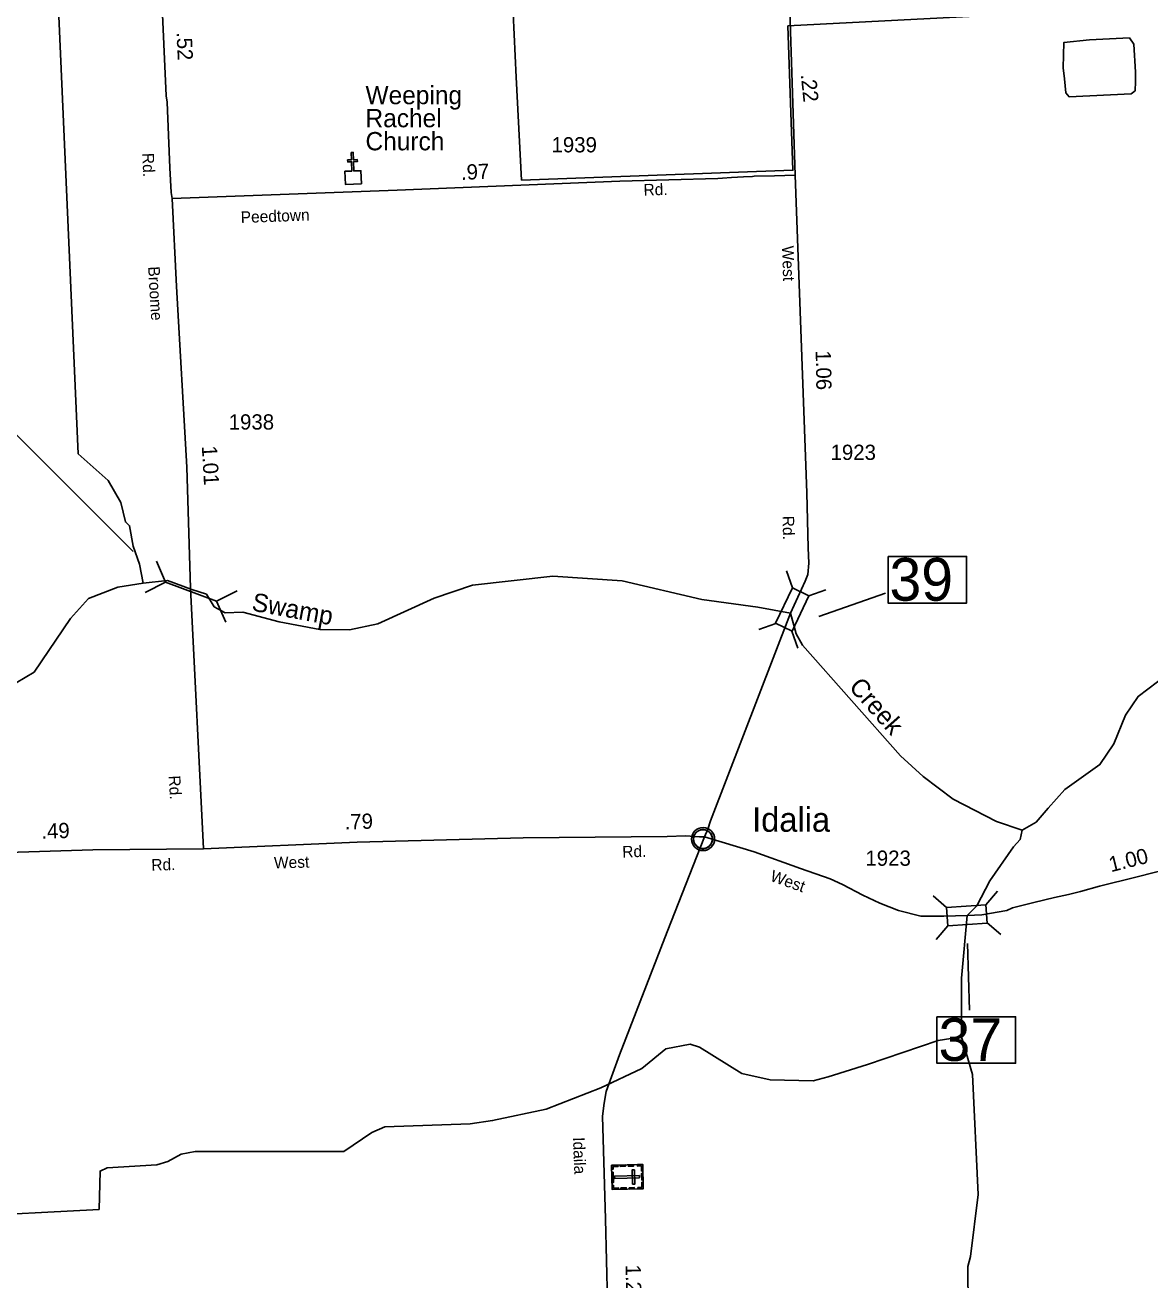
# Model space of a CAD drawing. Extents: x 2532689 to 2764727, y 536648 to 732970.
# Drawn here: x 2653505 to 2662724, y 560516 to 570801 of the extents above; entities that cross this region are included whole.
import ezdxf

# ---------------------------------------------------------------- set-up
doc = ezdxf.new("R2010")
doc.units = 0
for name, color, linetype in [('Exist Boundary Political City Limit New', 7, 'Continuous'), ('Exist Civil Demographics Community CELL', 7, 'Continuous'), ('Exist Civil Demographics Community Label', 7, 'Continuous'), ('Exist Cultural Cemetery CELL', 7, 'Continuous'), ('Exist Cultural Church CELL', 7, 'Continuous'), ('Exist Cultural Church Label', 7, 'Continuous'), ('Exist Hydrographic Creek Single Shore', 7, 'Continuous'), ('Exist Hydrographic Creek Single Shore Label', 7, 'Continuous'), ('Exist Hydrographic Pond Under 1500 Sq Ft', 7, 'Continuous'), ('Exist Road Secondary Mileage Hundredths English Label', 7, 'Continuous'), ('Exist Road Secondary Structure Pipe CELL', 7, 'Continuous'), ('Exist Road Secondary Structure Pipe Number Label', 7, 'Continuous'), ('Exist Road Secondary Structure Standard Bridge CELL', 7, 'Continuous'), ('Exist Road Secondary Structure Standard Bridge Number Label', 7, 'Continuous'), ('Exist Road Secondary Type 20 Attributed', 7, 'Continuous'), ('Exist Road Secondary Type 51 Attributed', 7, 'Continuous'), ('Exist Road Secondary Type 51 Label', 7, 'Continuous'), ('Exist Road Secondary Type 51 Number Label', 7, 'Continuous'), ('Map Preparation Boundary City Limit Buffer Line', 7, 'Continuous')]:
    doc.layers.add(name, color=color, linetype=linetype)

msp = doc.modelspace()

# ---------------------------------------------------------------- linework, layer by layer
at = {"layer": 'Exist Boundary Political City Limit New'}
for points in [[(2659756, 570796), (2659798, 569611), (2657575, 569531), (2657530, 570375), (2657498, 571076)], [(2663735, 571000), (2659756, 570796)]]:
    msp.add_lwpolyline(points, dxfattribs=at)
at = {"layer": 'Exist Civil Demographics Community CELL'}
msp.add_lwpolyline([(2658984, 564141), (2658985, 564147), (2658987, 564154), (2658990, 564161), (2658993, 564167), (2658996, 564172), (2659000, 564177), (2659004, 564182), (2659008, 564186), (2659014, 564191), (2659019, 564195), (2659024, 564198), (2659029, 564200), (2659035, 564202), (2659040, 564204), (2659044, 564205), (2659049, 564206), (2659053, 564207), (2659060, 564207), (2659064, 564207), (2659070, 564207), (2659075, 564206), (2659080, 564205), (2659085, 564203), (2659090, 564202), (2659097, 564199), (2659103, 564195), (2659108, 564192), (2659113, 564188), (2659116, 564184), (2659120, 564180), (2659124, 564175), (2659127, 564171), (2659131, 564166), (2659133, 564161), (2659135, 564156), (2659137, 564151), (2659138, 564146), (2659139, 564140), (2659140, 564135), (2659140, 564129), (2659140, 564123), (2659139, 564118), (2659138, 564112), (2659137, 564106), (2659135, 564100), (2659132, 564095), (2659129, 564089), (2659126, 564084), (2659122, 564079), (2659118, 564074), (2659113, 564069), (2659108, 564065), (2659103, 564062), (2659099, 564059), (2659092, 564056), (2659085, 564053), (2659079, 564052), (2659072, 564051), (2659068, 564050), (2659063, 564050), (2659058, 564050), (2659053, 564050), (2659048, 564051), (2659042, 564052), (2659037, 564054), (2659032, 564056), (2659027, 564058), (2659023, 564060), (2659017, 564064), (2659011, 564068), (2659006, 564073), (2659002, 564078), (2658999, 564081), (2658996, 564086), (2658991, 564093), (2658990, 564096), (2658988, 564100), (2658985, 564109), (2658984, 564116), (2658983, 564121), (2658983, 564127), (2658983, 564132), (2658983, 564138)], close=True, dxfattribs=at)
for centre, radius in [((2659062, 564129), 94.3), ((2659061, 564129), 76.7)]:
    msp.add_circle(centre, radius, dxfattribs=at)
at = {"layer": 'Exist Cultural Cemetery CELL'}
for points in [[(2658567, 561462), (2658572, 561263), (2658317, 561256), (2658312, 561455)], [(2658313, 561422), (2658325, 561423), (2658324, 561445), (2658365, 561446), (2658364, 561457), (2658312, 561455)], [(2658382, 561457), (2658426, 561458), (2658426, 561447), (2658383, 561446)], [(2658449, 561459), (2658493, 561460), (2658493, 561448), (2658450, 561447)], [(2658500, 561419), (2658481, 561419), (2658484, 561301), (2658503, 561301)], [(2658524, 561461), (2658524, 561449), (2658556, 561450), (2658557, 561409), (2658568, 561410), (2658567, 561462)], [(2658325, 561398), (2658327, 561313), (2658316, 561313), (2658314, 561398)], [(2658540, 561352), (2658540, 561371), (2658337, 561366), (2658338, 561347)], [(2658528, 561261), (2658528, 561273), (2658560, 561274), (2658559, 561314), (2658570, 561314), (2658572, 561263)], [(2658569, 561388), (2658570, 561336), (2658559, 561335), (2658557, 561387)], [(2658316, 561289), (2658328, 561290), (2658328, 561268), (2658369, 561269), (2658369, 561258), (2658317, 561256)], [(2658389, 561270), (2658432, 561271), (2658433, 561259), (2658389, 561258)], [(2658455, 561271), (2658498, 561272), (2658499, 561261), (2658455, 561260)]]:
    msp.add_lwpolyline(points, close=True, dxfattribs=at)
at = {"layer": 'Exist Cultural Church CELL'}
msp.add_lwpolyline([(2656127, 569603), (2656183, 569605), (2656181, 569681), (2656149, 569680), (2656148, 569696), (2656180, 569697), (2656178, 569757), (2656194, 569758), (2656196, 569698), (2656228, 569699), (2656229, 569683), (2656197, 569682), (2656199, 569606), (2656257, 569608), (2656261, 569501), (2656130, 569496)], close=True, dxfattribs=at)
at = {"layer": 'Exist Hydrographic Creek Single Shore'}
for points in [[(2654472, 566226), (2654443, 566383), (2654390, 566531), (2654361, 566698), (2654327, 566729), (2654290, 566889), (2654186, 567068), (2653940, 567288), (2653757, 571434), (2653723, 571837), (2653654, 572300), (2653667, 572458)], [(2661677, 564202), (2661467, 564273), (2661113, 564455), (2660867, 564642), (2660680, 564812), (2659876, 565719), (2659824, 565812), (2659779, 565981), (2659511, 566029), (2659051, 566093), (2658398, 566247), (2657830, 566283), (2657173, 566210), (2656858, 566103), (2656396, 565893), (2656165, 565845), (2655922, 565848), (2655587, 565910), (2655289, 565989), (2655144, 565983), (2655055, 566033), (2654991, 566136), (2654872, 566174), (2654672, 566249), (2654472, 566226)], [(2650468, 564078), (2650420, 565902), (2650469, 565920), (2651260, 565955), (2651562, 565885), (2651950, 565688), (2652300, 565652), (2653248, 565399), (2653431, 565409), (2653579, 565497), (2653878, 565936), (2654024, 566100), (2654264, 566195), (2654472, 566226)], [(2661677, 564202), (2661792, 564269), (2661890, 564382), (2662028, 564535), (2662315, 564740), (2662428, 564909), (2662523, 565146), (2662628, 565298), (2662866, 565478)], [(2661181, 562508), (2661179, 562990), (2661226, 563502), (2661307, 563583), (2661412, 563786), (2661605, 564065), (2661662, 564126), (2661677, 564202)], [(2652953, 561033), (2654111, 561093), (2654120, 561408), (2654178, 561434), (2654585, 561460), (2654676, 561487), (2654783, 561547), (2654900, 561568), (2656117, 561568), (2656347, 561725), (2656454, 561769), (2657154, 561794), (2657337, 561821), (2657776, 561914), (2658223, 562089), (2658561, 562248), (2658757, 562410), (2658957, 562448), (2659032, 562424), (2659379, 562208), (2659613, 562156), (2659963, 562147), (2660088, 562181), (2660411, 562280), (2660990, 562477), (2661181, 562508)], [(2661318, 561216), (2661271, 562199), (2661181, 562508)], [(2661344, 557744), (2661396, 557807), (2661487, 557947), (2661559, 558580), (2661555, 558773), (2661482, 559053), (2661456, 559088), (2661266, 559799), (2661237, 559956), (2661231, 560625), (2661254, 560708), (2661318, 561216)]]:
    msp.add_lwpolyline(points, dxfattribs=at)
at = {"layer": 'Exist Hydrographic Pond Under 1500 Sq Ft'}
for points in [[(2662606, 570415), (2662593, 570645), (2662556, 570696), (2662230, 570681), (2662019, 570659), (2662014, 570452), (2662024, 570360)], [(2662024, 570360), (2662036, 570246), (2662062, 570214), (2662571, 570238), (2662603, 570263), (2662605, 570339), (2662606, 570415)]]:
    msp.add_lwpolyline(points, dxfattribs=at)
at = {"layer": 'Exist Road Secondary Structure Pipe CELL'}
for p, q in [((2654582, 566407), (2654656, 566234)), ((2654488, 566151), (2654656, 566234)), ((2654656, 566234), (2655075, 566080)), ((2655243, 566163), (2655075, 566080)), ((2655149, 565908), (2655075, 566080))]:
    msp.add_line(p, q, dxfattribs=at)
at = {"layer": 'Exist Road Secondary Structure Pipe Number Label'}
msp.add_line((2654391, 566486), (2651863, 569014), dxfattribs=at)
at = {"layer": 'Exist Road Secondary Structure Standard Bridge CELL'}
for p, q in [((2659746, 566327), (2659795, 566189)), ((2660069, 566172), (2659930, 566123)), ((2659657, 565897), (2659519, 565848)), ((2659790, 565833), (2659839, 565694)), ((2661380, 563590), (2661476, 563701)), ((2660947, 563663), (2661058, 563567)), ((2660973, 563306), (2661069, 563417)), ((2661390, 563443), (2661502, 563347))]:
    msp.add_line(p, q, dxfattribs=at)
for points in [[(2659930, 566123), (2659791, 565833), (2659655, 565898), (2659795, 566189)], [(2661058, 563567), (2661380, 563591), (2661391, 563440), (2661069, 563417)]]:
    msp.add_lwpolyline(points, close=True, dxfattribs=at)
at = {"layer": 'Exist Road Secondary Structure Standard Bridge Number Label'}
for p, q in [((2660010, 565953), (2660556, 566146)), ((2661230, 563272), (2661246, 562726))]:
    msp.add_line(p, q, dxfattribs=at)
for points in [[(2660578, 566446), (2661222, 566446), (2661222, 566064), (2660578, 566064)], [(2660979, 562673), (2661623, 562673), (2661623, 562291), (2660979, 562291)]]:
    msp.add_lwpolyline(points, close=True, dxfattribs=at)
at = {"layer": 'Exist Road Secondary Type 20 Attributed'}
for points in [[(2654711, 569380), (2654702, 569428), (2654691, 569632), (2654681, 569900), (2654669, 570169), (2654662, 570221), (2654622, 571072), (2654556, 572078)], [(2654966, 564048), (2654862, 566186), (2654832, 567178), (2654745, 568659), (2654711, 569380)], [(2654966, 564048), (2654061, 564041), (2653009, 564008), (2652563, 564000), (2652417, 563996), (2652363, 563993)]]:
    msp.add_lwpolyline(points, dxfattribs=at)
at = {"layer": 'Exist Road Secondary Type 51 Attributed'}
for points in [[(2659749, 571677), (2659816, 569571)], [(2654711, 569380), (2656554, 569447), (2658381, 569523), (2659182, 569545), (2659220, 569546), (2659296, 569552), (2659394, 569558), (2659468, 569561), (2659480, 569562), (2659648, 569567), (2659816, 569571)], [(2659816, 569571), (2659913, 566967), (2659923, 566517), (2659930, 566391), (2659920, 566297), (2659899, 566242), (2659779, 565981)], [(2659779, 565981), (2659122, 564278), (2659100, 564211), (2659074, 564148)], [(2663911, 564195), (2663852, 564151), (2663724, 564104), (2663491, 564035), (2663254, 563976), (2663147, 563950), (2662920, 563897), (2662608, 563818), (2662311, 563743), (2662156, 563700), (2662058, 563676), (2661943, 563649), (2661774, 563609), (2661597, 563565), (2661553, 563544), (2661348, 563509), (2661226, 563502)], [(2659074, 564148), (2659033, 564148), (2658919, 564157), (2658767, 564151), (2657587, 564139), (2656228, 564103), (2654966, 564048)], [(2659074, 564148), (2658769, 563370), (2658376, 562361), (2658268, 562059), (2658251, 561965), (2658239, 561858), (2658263, 561013), (2658279, 560335), (2658330, 559228), (2658356, 558203), (2658350, 557969), (2658352, 557835)], [(2661226, 563502), (2661034, 563497), (2660848, 563497), (2660665, 563543), (2660512, 563603), (2660372, 563670), (2660206, 563756), (2660103, 563802), (2659861, 563889), (2659480, 564025), (2659074, 564148)]]:
    msp.add_lwpolyline(points, dxfattribs=at)
at = {"layer": 'Map Preparation Boundary City Limit Buffer Line'}
for points in [[(2659756, 570796), (2659798, 569611), (2657575, 569531), (2657530, 570375), (2657498, 571076)], [(2663735, 571000), (2659756, 570796)]]:
    msp.add_lwpolyline(points, dxfattribs=at)

# ---------------------------------------------------------------- texts
at = {"layer": 'Exist Civil Demographics Community Label'}
msp.add_text('Idalia', height=200, dxfattribs=at).set_placement((2659464, 564189))
at = {"layer": 'Exist Cultural Church Label'}
for s, p in [('Weeping', (2656295, 570153)), ('Rachel', (2656295, 569964)), ('Church', (2656295, 569775))]:
    msp.add_text(s, height=150, dxfattribs=at).set_placement(p)
at = {"layer": 'Exist Hydrographic Creek Single Shore Label'}
for s, rotation, p in [('Swamp', 349.5054, (2655356, 566003)), ('Creek', 311.5756, (2660250, 565371))]:
    msp.add_text(s, height=150, rotation=rotation, dxfattribs=at).set_placement(p)
at = {"layer": 'Exist Road Secondary Mileage Hundredths English Label'}
for s, rotation, p in [('.52', 272.7307, (2654746, 570742)), ('.22', 275.984, (2659862, 570396)), ('.97', 2.395, (2657080, 569532)), ('1.06', 270.9999, (2659985, 568134)), ('1.01', 273.3508, (2654953, 567350)), ('.79', 1.9066, (2656126, 564207)), ('.49', 1.8121, (2653640, 564131)), ('1.00', 14.08, (2662405, 563857)), ('1.20', 271.3998, (2658426, 560640))]:
    msp.add_text(s, height=125, rotation=rotation, dxfattribs=at).set_placement(p)
at = {"layer": 'Exist Road Secondary Structure Standard Bridge Number Label'}
for s, p in [('39', (2660590, 566083)), ('37', (2660992, 562311))]:
    msp.add_text(s, height=350, dxfattribs=at).set_placement(p)
at = {"layer": 'Exist Road Secondary Type 51 Label'}
for s, rotation, p in [('Rd.', 272.101, (2654466, 569752)), ('Rd.', 1.5391, (2658575, 569404)), ('Peedtown', 2.0783, (2655274, 569179)), ('West', 271.8901, (2659709, 568991)), ('Broome', 273.3508, (2654513, 568821)), ('Rd.', 271.2674, (2659713, 566778)), ('Rd.', 273.0107, (2654682, 564648)), ('Rd.', 1.9066, (2658401, 563977)), ('West', 1.4706, (2655546, 563888)), ('Rd.', 1.9927, (2654541, 563869)), ('West', 340.2674, (2659605, 563789)), ('Idaila', 272.0044, (2657996, 561684))]:
    msp.add_text(s, height=95, rotation=rotation, dxfattribs=at).set_placement(p)
at = {"layer": 'Exist Road Secondary Type 51 Number Label'}
for s, p in [('1939', (2657820, 569758)), ('1938', (2655174, 567486)), ('1923', (2660107, 567237)), ('1923', (2660393, 563910))]:
    msp.add_text(s, height=125, dxfattribs=at).set_placement(p)

doc.saveas('drawing.dxf')
